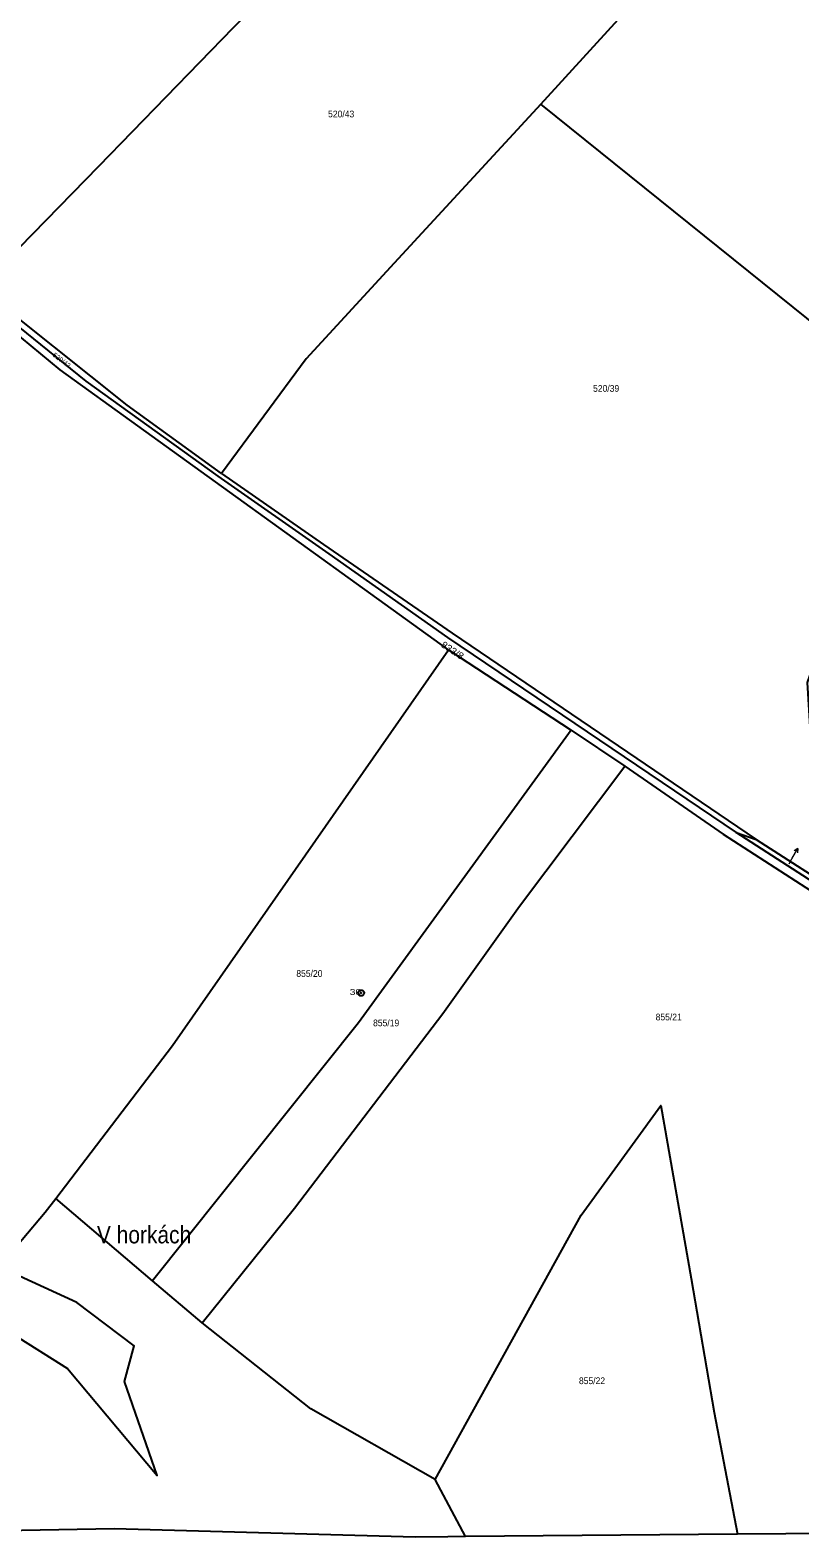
# Model space of a CAD drawing. Extents: x -687135 to -684370, y -1007309 to -1005782.
# Drawn here: x -685826.9 to -685632.3, y -1007305.6 to -1006924.3 of the extents above; entities that cross this region are included whole.
import ezdxf
from ezdxf.enums import TextEntityAlignment as Align

# ---------------------------------------------------------------- set-up
doc = ezdxf.new("R2010")
doc.units = 0
doc.header["$LTSCALE"] = 0.68
for name, color, linetype, lineweight in [('1', 7, 'Continuous', 25), ('7', 7, 'Continuous', 13), ('8', 7, 'Continuous', 25)]:
    doc.layers.add(name, color=color, linetype=linetype, lineweight=lineweight)
doc.layers.add('2', color=7, linetype='Continuous')

msp = doc.modelspace()

# ---------------------------------------------------------------- linework, layer by layer
at = {"layer": '1'}
for p, q in [((-685697.79, -1006943.02), (-685662.46, -1006904.3)), ((-685648.4, -1007127.2), (-685643.28, -1007129)), ((-685716.84, -1007305.32), (-685724.46, -1007290.91)), ((-685648.07, -1007304.74), (-685716.84, -1007305.32)), ((-685612.11, -1007304.44), (-685648.07, -1007304.74))]:
    msp.add_line(p, q, dxfattribs=at)
for points in [[(-685839.55, -1006989.44), (-685809.54, -1006958.71), (-685775.47, -1006923.66), (-685749.74, -1006897.67), (-685716.52, -1006867.72), (-685765.63, -1006834.08)], [(-685983.96, -1006904.85), (-685958.47, -1006914.12), (-685916.47, -1006935.45), (-685893.9, -1006949.53), (-685878.72, -1006960.5), (-685861.45, -1006973.3), (-685848.73, -1006983.28), (-685831.73, -1006997.72), (-685812.81, -1007013.08), (-685779.43, -1007037.13), (-685751.37, -1007056.79), (-685721.37, -1007077.91), (-685689.18, -1007099.67), (-685648.4, -1007127.2)], [(-685697.79, -1006943.02), (-685734.8, -1006983.19), (-685757.1, -1007007.46), (-685778.52, -1007036.46)], [(-685617.35, -1007144.84), (-685628.86, -1007114.49), (-685630.33, -1007089.27), (-685620.78, -1007062.3), (-685600.31, -1007021.4), (-685697.79, -1006943.02)], [(-685721.07, -1007081.01), (-685819.28, -1007010.22), (-685841.33, -1006991.98), (-685846.06, -1006988.01)], [(-685778.52, -1007036.46), (-685802.3, -1007019.17), (-685839.55, -1006989.44)], [(-685778.52, -1007036.46), (-685752.67, -1007054.36), (-685720.15, -1007076.81), (-685643.28, -1007129)], [(-685820.34, -1007219.84), (-685790.89, -1007181.07), (-685721.07, -1007081.01)], [(-685721.07, -1007081.01), (-685690.12, -1007101.36), (-685676.52, -1007110.47)], [(-685690.12, -1007101.36), (-685743.89, -1007175.37), (-685795.95, -1007240.65)], [(-685783.37, -1007251.26), (-685760.05, -1007222.27), (-685722.57, -1007173), (-685703.14, -1007145.83), (-685676.52, -1007110.47)], [(-685676.52, -1007110.47), (-685651.64, -1007127.65), (-685622.91, -1007146.17), (-685616.25, -1007148.85), (-685616.95, -1007146.31)], [(-685616.95, -1007146.31), (-685621.04, -1007144.83), (-685648.4, -1007127.2)], [(-685643.28, -1007129), (-685620.51, -1007143.68), (-685617.35, -1007144.84)], [(-685724.46, -1007290.91), (-685687.6, -1007224.04), (-685667.46, -1007196.26), (-685659.78, -1007240.06), (-685653.94, -1007273.89), (-685648.07, -1007304.74)], [(-685834.78, -1007237.06), (-685823.03, -1007223.25), (-685820.34, -1007219.84)], [(-685783.37, -1007251.26), (-685795.95, -1007240.65), (-685820.34, -1007219.84)], [(-685937.16, -1007230.29), (-685845.31, -1007245.22), (-685817.39, -1007262.76), (-685794.79, -1007289.87), (-685803.04, -1007266.06), (-685800.57, -1007257.03), (-685815.07, -1007246.11), (-685834.78, -1007237.06)], [(-685724.46, -1007290.91), (-685755.91, -1007273.04), (-685783.37, -1007251.26)], [(-685716.84, -1007305.32), (-685721.26, -1007305.36), (-685729.55, -1007305.43), (-685805.63, -1007303.31), (-685931.97, -1007305.63)]]:
    msp.add_lwpolyline(points, dxfattribs=at)
at = {"layer": '7'}
msp.add_line((-685632.825, -1007131.275), (-685633.749, -1007131.908), dxfattribs=at)
msp.add_lwpolyline([(-685634.98, -1007135.16), (-685634.28, -1007133.9), (-685632.825, -1007131.275), (-685632.873, -1007132.394)], dxfattribs=at)
at = {"layer": '8'}
for radius in [0.75, 0.03]:
    msp.add_circle((-685743.17, -1007167.8198), radius, dxfattribs=at)

# ---------------------------------------------------------------- texts
at = {"layer": '2', "width": 0.95}
for s, p in [('520/43', (-685751.54, -1006946.35)), ('520/39', (-685684.55, -1007015.76)), ('855/20', (-685759.57, -1007163.75)), ('855/19', (-685740.17, -1007176.24)), ('855/21', (-685668.73, -1007174.75)), ('855/22', (-685688.12, -1007266.75))]:
    msp.add_text(s, height=1.7, dxfattribs=at).set_placement(p)
at = {"layer": '2'}
for s, height, rotation, width, p in [('520/42', 1.19, 323, 1.05, (-685821.278, -1007006.705)), ('833/8', 1.7, 327, 1.1, (-685723.172, -1007080.172))]:
    msp.add_text(s, height=height, rotation=rotation, dxfattribs=dict(at, width=width)).set_placement(p)
at = {"layer": '7', "width": 0.9}
msp.add_text('V horkách', height=4.4, dxfattribs=at).set_placement((-685798.069, -1007231.149), align=Align.CENTER)
at = {"layer": '8', "width": 1.3}
msp.add_text('30', height=1.5, dxfattribs=at).set_placement((-685743.169, -1007168.32), align=Align.RIGHT)

doc.saveas('drawing.dxf')
